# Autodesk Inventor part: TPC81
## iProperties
Shininess: 64.0
Length Units: 11272
Angle Units: 11279
Time Units: 11290
Mass Units: 11286
Length Display Precision: 3
Angle Display Precision: 2
Compacted: True
Part Number: TPC81
Document SubType Name: Modeling
Created: 2004-08
Designer: Lori
Manufacturer: Standard
Standards Organization: Custom
Density: 0.0
Volumn: 0.0
Area: 0.0
PropertySet Name: Model Information
Control State: 0
Master: False
Checked Out: False
Author: Lori
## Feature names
1. Base1
